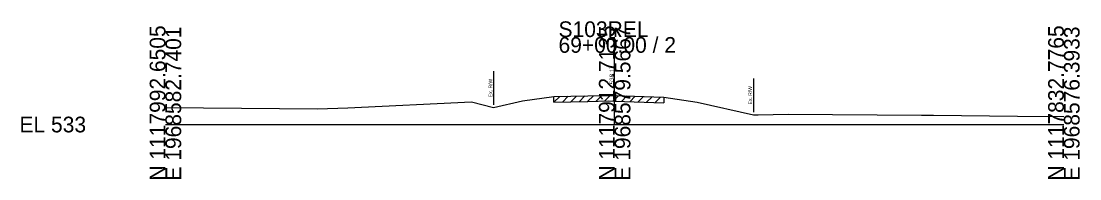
# Model space of a CAD drawing. Extents: x -26 to 163, y -10 to 24518.
# Drawn here: x -25.7 to 162.8, y 17490.3 to 17518.4 of the extents above; entities that cross this region are included whole.
import ezdxf

# ---------------------------------------------------------------- set-up
doc = ezdxf.new("R2010")
doc.units = 0
for name, color, linetype in [('RD_GPK_XS_Cell', 7, 'Continuous'), ('RD_XS_ExGround', 7, 'Continuous'), ('RD_XS_ExPaveRet', 7, 'Continuous'), ('RD_XS_ExRW', 7, 'Continuous'), ('RD_XS_TX_Elev_EX', 7, 'Continuous')]:
    doc.layers.add(name, color=color, linetype=linetype)

msp = doc.modelspace()

# ---------------------------------------------------------------- linework, layer by layer
at = {"layer": 'RD_GPK_XS_Cell'}
for p, q in [((80, 17500), (80, 17515.6)), ((0, 17500), (80, 17500)), ((80, 17500), (160, 17500))]:
    msp.add_line(p, q, dxfattribs=at)
at = {"layer": 'RD_XS_ExGround'}
msp.add_lwpolyline([(0, 17503.06), (27.05, 17502.78), (32.49, 17503), (54.5, 17504.04), (58.45, 17503.02), (63.58, 17504.2), (69.19, 17504.97), (75.2, 17505.11), (78.99, 17505.2), (80, 17505.17), (88.78, 17504.87), (94.7, 17504.01), (104.7, 17501.72), (105.58, 17501.74), (110.91, 17501.86), (134.62, 17501.67), (136.81, 17501.66), (151.72, 17501.51), (160, 17501.44)], dxfattribs=at)
at = {"layer": 'RD_XS_ExPaveRet'}
for p, q in [((69.19, 17503.97), (70.21, 17504.99)), ((69.19, 17503.97), (69.19, 17504.97)), ((69.19, 17503.97), (75.2, 17504.11)), ((70.69, 17504), (71.71, 17505.03)), ((72.19, 17504.04), (73.21, 17505.06)), ((73.69, 17504.07), (74.71, 17505.1)), ((75.19, 17504.11), (76.21, 17505.13)), ((75.2, 17504.11), (78.99, 17504.2)), ((76.69, 17504.14), (77.71, 17505.17)), ((78.19, 17504.18), (79.2, 17505.19)), ((78.99, 17504.2), (80, 17504.17)), ((79.69, 17504.18), (80.66, 17505.14)), ((80, 17504.17), (88.78, 17503.87)), ((81.19, 17504.12), (82.16, 17505.09)), ((82.69, 17504.07), (83.66, 17505.04)), ((84.19, 17504.02), (85.16, 17504.99)), ((85.69, 17503.97), (86.66, 17504.94)), ((87.19, 17503.92), (88.16, 17504.89)), ((88.78, 17504.87), (88.78, 17503.87))]:
    msp.add_line(p, q, dxfattribs=at)
at = {"layer": 'RD_XS_ExRW'}
for p, q in [((58.45, 17509.52), (58.45, 17503.52)), ((104.7, 17508.22), (104.7, 17502.22))]:
    msp.add_line(p, q, dxfattribs=at)

# ---------------------------------------------------------------- texts
at = {"layer": 'RD_GPK_XS_Cell'}
for s, p in [('N 1117992.6505', (0, 17490)), ('E 1968582.7401', (2.8, 17490)), ('N 1117912.7135', (80, 17490)), ('E 1968579.5667', (82.8, 17490)), ('N 1117832.7765', (160, 17490)), ('E 1968576.3933', (162.8, 17490))]:
    msp.add_text(s, height=2.8, rotation=90, dxfattribs=at).set_placement(p)
for s, p in [('S103REL', (70, 17515.6)), ('69+00.00 / 2', (70, 17512.8)), ('EL 533', (-26, 17498.6))]:
    msp.add_text(s, height=2.8, dxfattribs=at).set_placement(p)
at = {"layer": 'RD_XS_ExRW'}
for p in [(58.2, 17504.87), (104.45, 17503.57)]:
    msp.add_text('Ex. R/W ', height=0.65, rotation=90, dxfattribs=at).set_placement(p)
at = {"layer": 'RD_XS_TX_Elev_EX'}
msp.add_text('538.17', height=0.8, rotation=90, dxfattribs=at).set_placement((79.9, 17507.17))

doc.saveas('drawing.dxf')
